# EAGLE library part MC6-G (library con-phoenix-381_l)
Mini-Combicon 3.81mm horizontal 6-polig (mit Gegenstecker)
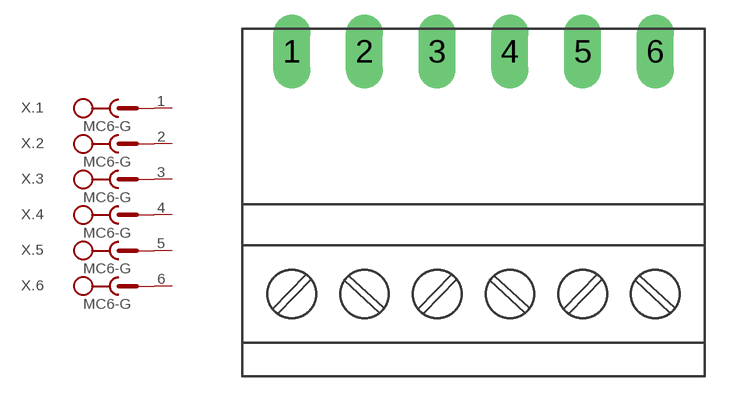
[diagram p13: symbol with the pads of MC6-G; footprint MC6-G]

Designator prefix X; gates .1=SK+V .2=SK+V .3=SK+V .4=SK+V .5=SK+V .6=SK+V

## MC6-G  [MC6-G]
1  .1:SK  pas
2  .2:SK  pas
3  .3:SK  pas
4  .4:SK  pas
5  .5:SK  pas
6  .6:SK  pas

## Footprint MC6-G (pad centres in mm)
Mini-Combicon 3.81mm horizontal 6-polig (mit Gegenstecker)
drill 1.3 long: 1 -9.525,0; 2 -5.715,0; 3 -1.905,0; 4 1.905,0; 5 5.715,0; 6 9.525,0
